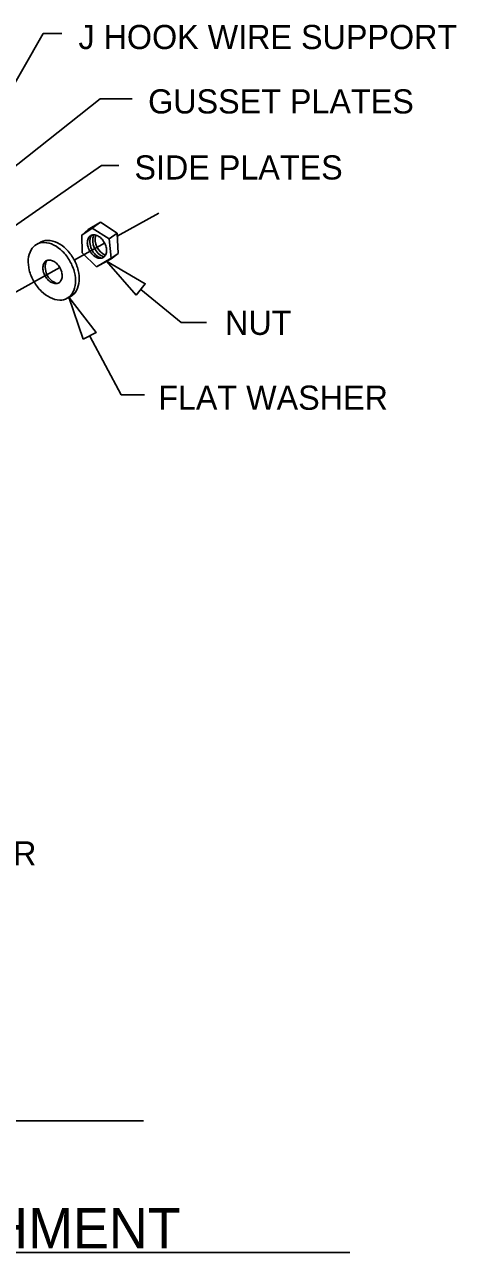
# Model space of a CAD drawing. Extents: x -1551.93 to -1544.71, y 2060.77 to 2070.61.
# Drawn here: x -1548.026 to -1546.954, y 2067.559 to 2070.609 of the extents above; entities that cross this region are included whole.
import ezdxf

# ---------------------------------------------------------------- set-up
doc = ezdxf.new("R2010")
doc.units = 0
for name, color, linetype in [('DETL-DIMS', 7, 'Continuous'), ('DETL-LINE', 7, 'Continuous'), ('DETL-NOTE', 7, 'Continuous'), ('DETL-TITL', 7, 'Continuous')]:
    doc.layers.add(name, color=color, linetype=linetype)

msp = doc.modelspace()

# ---------------------------------------------------------------- linework, layer by layer
at = {"layer": 'DETL-DIMS'}
for p, q in [((-1548.0776, 2070.415), (-1547.9806, 2070.587)), ((-1547.9806, 2070.587), (-1547.9336, 2070.587)), ((-1548.1906, 2070.146), (-1547.8386, 2070.424)), ((-1547.8386, 2070.424), (-1547.7596, 2070.424)), ((-1548.0626, 2070.101), (-1547.8356, 2070.259)), ((-1547.8356, 2070.259), (-1547.7926, 2070.259)), ((-1547.7966, 2070.083), (-1547.6926, 2070.14)), ((-1548.0756, 2069.929), (-1547.9386, 2070.005)), ((-1547.7376, 2069.951), (-1547.6376, 2069.869)), ((-1547.6376, 2069.869), (-1547.5746, 2069.869)), ((-1547.8646, 2069.835), (-1547.7866, 2069.689)), ((-1547.7866, 2069.689), (-1547.7286, 2069.689))]:
    msp.add_line(p, q, dxfattribs=at)
for points in [[(-1547.7496, 2069.937), (-1547.7266, 2069.965), (-1547.8226, 2070.021)], [(-1547.8806, 2069.827), (-1547.8486, 2069.844), (-1547.9166, 2069.932)]]:
    msp.add_lwpolyline(points, close=True, dxfattribs=at)
at = {"layer": 'DETL-LINE'}
for p, q in [((-1547.8586, 2070.103), (-1547.8846, 2070.086)), ((-1547.8686, 2070.1), (-1547.8846, 2070.086)), ((-1547.8376, 2070.118), (-1547.8686, 2070.1)), ((-1547.8586, 2070.103), (-1547.8376, 2070.118)), ((-1547.8166, 2070.077), (-1547.8586, 2070.103)), ((-1547.8376, 2070.118), (-1547.7966, 2070.091)), ((-1547.9036, 2070.024), (-1547.8276, 2070.066)), ((-1547.8846, 2070.086), (-1547.8836, 2070.042)), ((-1547.8166, 2070.077), (-1547.7966, 2070.091)), ((-1547.8116, 2070.029), (-1547.8166, 2070.077)), ((-1547.7966, 2070.091), (-1547.7936, 2070.04)), ((-1547.8836, 2070.042), (-1547.8476, 2070.007)), ((-1547.8116, 2070.029), (-1547.7936, 2070.04)), ((-1547.7936, 2070.04), (-1547.8116, 2070.027)), ((-1547.8476, 2070.007), (-1547.8116, 2070.029)), ((-1547.8116, 2070.027), (-1547.8476, 2070.007))]:
    msp.add_line(p, q, dxfattribs=at)
for centre, radius, start, end in [((-1547.9794, 2070.0324), 0.0351, 119.7062, 151.5235), ((-1547.9794, 2070.0324), 0.0351, 87.8889, 119.7062), ((-1547.9701, 2070.0376), 0.0351, 87.8889, 128.0059), ((-1547.9802, 2070.0088), 0.0587, 63.4336, 87.8889), ((-1547.971, 2070.014), 0.0587, 63.4336, 87.8889), ((-1547.9909, 2069.9875), 0.0825, 45.164, 63.4336), ((-1547.9816, 2069.9927), 0.0825, 45.164, 63.4336), ((-1547.837, 2070.0669), 0.0336, 175.9788, 194.2484), ((-1547.8467, 2070.0675), 0.0239, 151.5235, 175.9788), ((-1547.8551, 2070.0721), 0.0143, 119.7062, 151.5235), ((-1547.8212, 2070.0689), 0.0429, 158.3047, 250.6427), ((-1547.8551, 2070.0721), 0.0143, 87.8889, 119.7062), ((-1547.8141, 2070.0718), 0.0429, 160.0479, 249.6903), ((-1547.8555, 2070.0625), 0.0239, 63.4336, 87.8889), ((-1547.8082, 2070.0753), 0.0429, 165.9012, 246.2203), ((-1547.8598, 2070.0539), 0.0336, 45.164, 63.4336), ((-1547.8691, 2070.0445), 0.0468, 29.7062, 45.164), ((-1547.8691, 2070.0445), 0.0468, 14.2484, 29.7062), ((-1547.9586, 2070.0212), 0.0587, 151.5235, 175.9788), ((-1548.0138, 2069.9645), 0.115, 29.7062, 45.164), ((-1548.0045, 2069.9697), 0.115, 29.7062, 45.164), ((-1547.8242, 2070.0701), 0.0468, 194.2484, 209.7062), ((-1547.8242, 2070.0701), 0.0468, 209.7062, 225.164), ((-1547.8335, 2070.0608), 0.0336, 225.164, 243.4336), ((-1547.8378, 2070.0521), 0.0239, 243.4336, 267.8889), ((-1547.8382, 2070.0425), 0.0143, 299.7062, 331.5235), ((-1547.8467, 2070.0471), 0.0239, 331.5235, 355.9788), ((-1547.8563, 2070.0477), 0.0336, 355.9788, 14.2484), ((-1547.9349, 2070.0195), 0.0825, 175.9788, 194.2484), ((-1547.9474, 2070.0043), 0.0336, 175.9788, 194.2484), ((-1547.957, 2070.0049), 0.0239, 151.5235, 175.9788), ((-1547.9655, 2070.0095), 0.0143, 119.7062, 151.5235), ((-1547.9322, 2070.0063), 0.0429, 158.3047, 250.9555), ((-1547.9655, 2070.0095), 0.0143, 87.8889, 119.7062), ((-1547.9658, 2069.9999), 0.0239, 63.4336, 87.8889), ((-1547.9702, 2069.9912), 0.0336, 45.164, 63.4336), ((-1547.9795, 2069.9819), 0.0468, 29.7062, 45.164), ((-1547.9795, 2069.9819), 0.0468, 14.2484, 29.7062), ((-1548.0138, 2069.9645), 0.115, 14.2484, 29.7062), ((-1548.0045, 2069.9697), 0.115, 14.2484, 29.7062), ((-1547.8382, 2070.0425), 0.0143, 267.8889, 299.7062), ((-1547.9034, 2070.0275), 0.115, 194.2484, 209.7062), ((-1547.9034, 2070.0275), 0.115, 209.7062, 225.164), ((-1547.9346, 2070.0075), 0.0468, 194.2484, 209.7062), ((-1547.9346, 2070.0075), 0.0468, 209.7062, 225.164), ((-1547.9439, 2069.9981), 0.0336, 225.164, 243.4336), ((-1547.9486, 2069.9798), 0.0143, 299.7062, 331.5235), ((-1547.957, 2069.9844), 0.0239, 331.5235, 355.9788), ((-1547.9667, 2069.9851), 0.0336, 355.9788, 14.2484), ((-1547.9823, 2069.9725), 0.0825, 355.9788, 14.2484), ((-1547.9493, 2069.976), 0.0587, 331.5235, 355.9788), ((-1547.9731, 2069.9777), 0.0825, 355.9788, 14.2484), ((-1547.9263, 2070.0045), 0.0825, 225.164, 243.4336), ((-1547.9482, 2069.9895), 0.0239, 243.4336, 267.8889), ((-1547.9486, 2069.9798), 0.0143, 267.8889, 299.7062), ((-1547.9378, 2069.9595), 0.0351, 299.7062, 331.5235), ((-1547.9285, 2069.9647), 0.0351, 299.7062, 331.5235), ((-1547.9586, 2069.9708), 0.0587, 331.5235, 355.9788), ((-1547.9369, 2069.9832), 0.0587, 243.4336, 267.8889), ((-1547.9378, 2069.9595), 0.0351, 267.8889, 299.7062), ((-1547.9285, 2069.9647), 0.0351, 290.6192, 299.7062)]:
    msp.add_arc(centre, radius, start, end, dxfattribs=at)
at = {"layer": 'DETL-TITL'}
for p, q in [((-1549.2969, 2067.8854), (-1547.7308, 2067.8854)), ((-1549.7443, 2067.5588), (-1547.2182, 2067.5588))]:
    msp.add_line(p, q, dxfattribs=at)

# ---------------------------------------------------------------- texts
at = {"layer": 'DETL-NOTE'}
for s, p in [('J HOOK WIRE SUPPORT', (-1547.8926, 2070.548)), ('GUSSET PLATES', (-1547.7196, 2070.388)), ('SIDE PLATES', (-1547.7536, 2070.224)), ('NUT', (-1547.5286, 2069.838)), ('FLAT WASHER', (-1547.6946, 2069.652)), ('INSTALL HOLE FOR RUBBER', (-1549.1116, 2068.52))]:
    msp.add_text(s, height=0.06, dxfattribs=at).set_placement(p)
at = {"layer": 'DETL-TITL'}
msp.add_text('ARM AND SIGNAL ATTACHMENT', height=0.100002, dxfattribs=at).set_placement((-1549.734, 2067.569))

doc.saveas('drawing.dxf')
